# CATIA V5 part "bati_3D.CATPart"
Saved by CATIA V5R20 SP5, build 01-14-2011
Part number: bati_3D
Publications: "Corps principal", "Arête", "Sommet", "Sommet1", "Face"
Bounding box of the stored display mesh (mm): x -29.961 to 50, y 0 to 500, z -29.976 to 29.961
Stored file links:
  C:\Users\Fox\Desktop\IAO Projet\A RENDRE\Sauvegarde IFMA\bati_3D.CATPart
  C:\Users\Fox\Desktop\IAO Projet\A RENDRE\Sauvegarde IFMA\mpeyrard.CATProduct
  C:\Users\Fox\Desktop\IAO Projet\A RENDRE\Sauvegarde IFMA\squelette_bati.CATPart
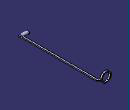
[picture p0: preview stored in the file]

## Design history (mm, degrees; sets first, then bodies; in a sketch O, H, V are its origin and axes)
Set1
  Point1 to Point3: linked copy from another document
  Plane1: linked copy from another document
  Line1: linked copy from another document
Body1 (main body)
  Sketch1 on Plane1, origin (0, 0, 0), H (0, 1, 0), V (0, 0, 1)
    line L1 (490, 30) -> (500, 30)
    line L2 (500, 30) -> (500, 25)
    line L3 (500, 25) -> (490, 25)
    line L4 (490, 25) -> (490, 30)
    point P3 (500, 25)
    reference projected point E1 (500, 0) from Point3
    reference projected point E2 (500, 0) from Point3
    point P5 (40, 15)
    point P6 (500, 0)
    reference projected point E3 (40, 15) from Point2
    reference projected point E4 (500, 0) from Point3
    angle L2 L1 = 90
    distance P3 E1 = 25
    distance P5 E3 = 0
    distance P6 E4 = 0
    length L2 = 5
    length L1 = 10
    parallelism: L4 L2, L1 L3
    coincidence: L2 E2
  Shaft1: profile Sketch1, axis Sketch1.H, angle 360
  Sketch2 on Plane1, origin (0, 0, 0), H (0, 1, 0), V (0, 0, 1)
    circle A1 centre (10, 0) radius 3
    point P1 (10, 0)
    reference projected point E1 (10, 0) from Point1
    circle A2 centre (10, 0) radius 10
    point P2 (10, 0)
    reference projected point E2 (10, 0) from Point1
    distance P1 E1 = 0
    distance P2 E2 = 0
    radius A2 = 10
  Pad1: profile Sketch2, direction (1, 0, 0), length 50, opposite side length -3
  Sketch3 on Plane1, origin (0, 0, 0), H (0, 1, 0), V (0, 0, 1)
    point P1 (13, 0)
    line L1 (13, 0) -> (13, 3.5)
    line L2 (13, 3.5) -> (500, 3.5)
    line L3 (500, 3.5) -> (500, -3.5)
    line L4 (500, -3.5) -> (13, -3.5)
    point P5 (13, -3.5)
    line L5 (13, -3.5) -> (13, 0)
    reference projected point E1 (10, 0) from Point1
    reference projected point E2 (500, 0) from Point3
    reference projected point E3 (10, 0) from Point1
    distance P1 E1 = 3
    distance L3 E2 = 0
    distance L4 E3 = 3.5
    distance L2 L4 = 7
    coincidence: P1 H, P5 L1
    vertical: L1 V, L3 V, L5 V
    horizontal: L2 H, L4 H
  Pad2: profile Sketch3, direction (1, 0, 0), length 50, opposite side length -40
  Sketch4 on start face of Pad2, origin (40, 0, 0), H (0, -1, 0), V (0, 0, 1)
    line L1 (-500, -3.5) -> (-490, -3.5)
    line L2 (-490, -3.5) -> (-490, 3.5)
    line L3 (-490, 3.5) -> (-500, 3.5)
    line L4 (-500, 3.5) -> (-500, -3.5)
    reference projected line E1 (-200, 3.5) -> (-13, 3.5) from edge [start face of Pad2 | face of Pad2 from Sketch3.L2]
    reference projected line E2 (-500, -3.5) -> (-500, 3.5) from edge [start face of Pad2 | face of Pad2 from Sketch3.L3]
    reference projected line E3 (-13, -3.5) -> (-200, -3.5) from edge [start face of Pad2 | face of Pad2 from Sketch3.L4]
    reference intersected line E4 through (-490, 0) direction (0, -1) from face of Shaft1 from Sketch1.L4
    distance L3 E1 = 0
    distance L4 E2 = 0
    distance L1 E3 = 0
    distance L2 E4 = 0
    horizontal: L1 H, L3 H
    vertical: L2 V, L4 V
  Pad3: profile Sketch4, direction (-1, 0, 0), up to the existing solid (limit type 2)
  Fillet1: radius 10, on edge [face of Shaft1 | face of Pad2]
